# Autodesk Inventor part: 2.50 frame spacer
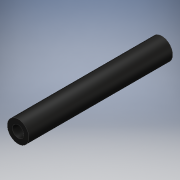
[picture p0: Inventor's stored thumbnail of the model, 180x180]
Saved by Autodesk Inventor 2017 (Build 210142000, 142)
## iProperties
Created: 2016-07
Part Number: 2.50 frame spacer
Material: Generic
Document SubType Name: Modeling
Designer: Stan
Density: 1 g/cm^3
Appearance: Glossy - Black
Author: Stan
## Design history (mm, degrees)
sketch "Sketch1"
  geometry: C1 r 4.763 at (0, 0); C2 r 2.54 at (0, 0); 1 further point
  constraints: 2 centre point, 2 coincident
  dimensions: "d0" = 9.525 diameter of C1; "d1" = 5.08 diameter of C2
extrude "Extrusion1" new body sketch "Sketch1" distance "d2" = 63.5; taper "d3" = 0 deg
body "Solid1"
